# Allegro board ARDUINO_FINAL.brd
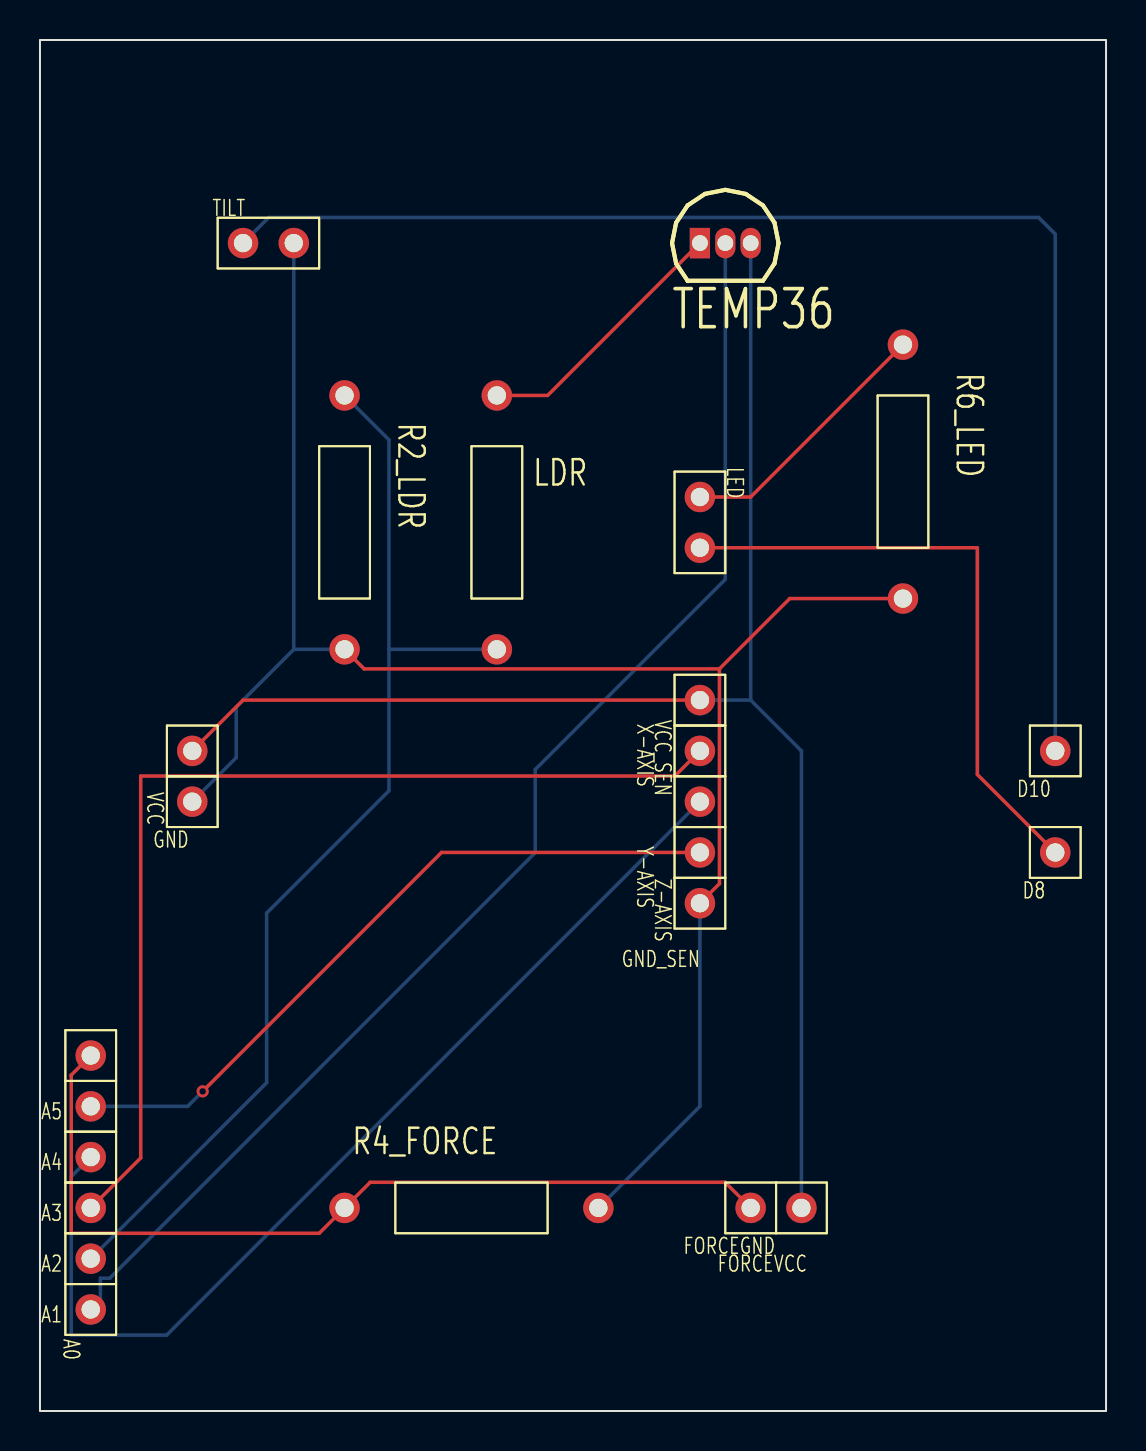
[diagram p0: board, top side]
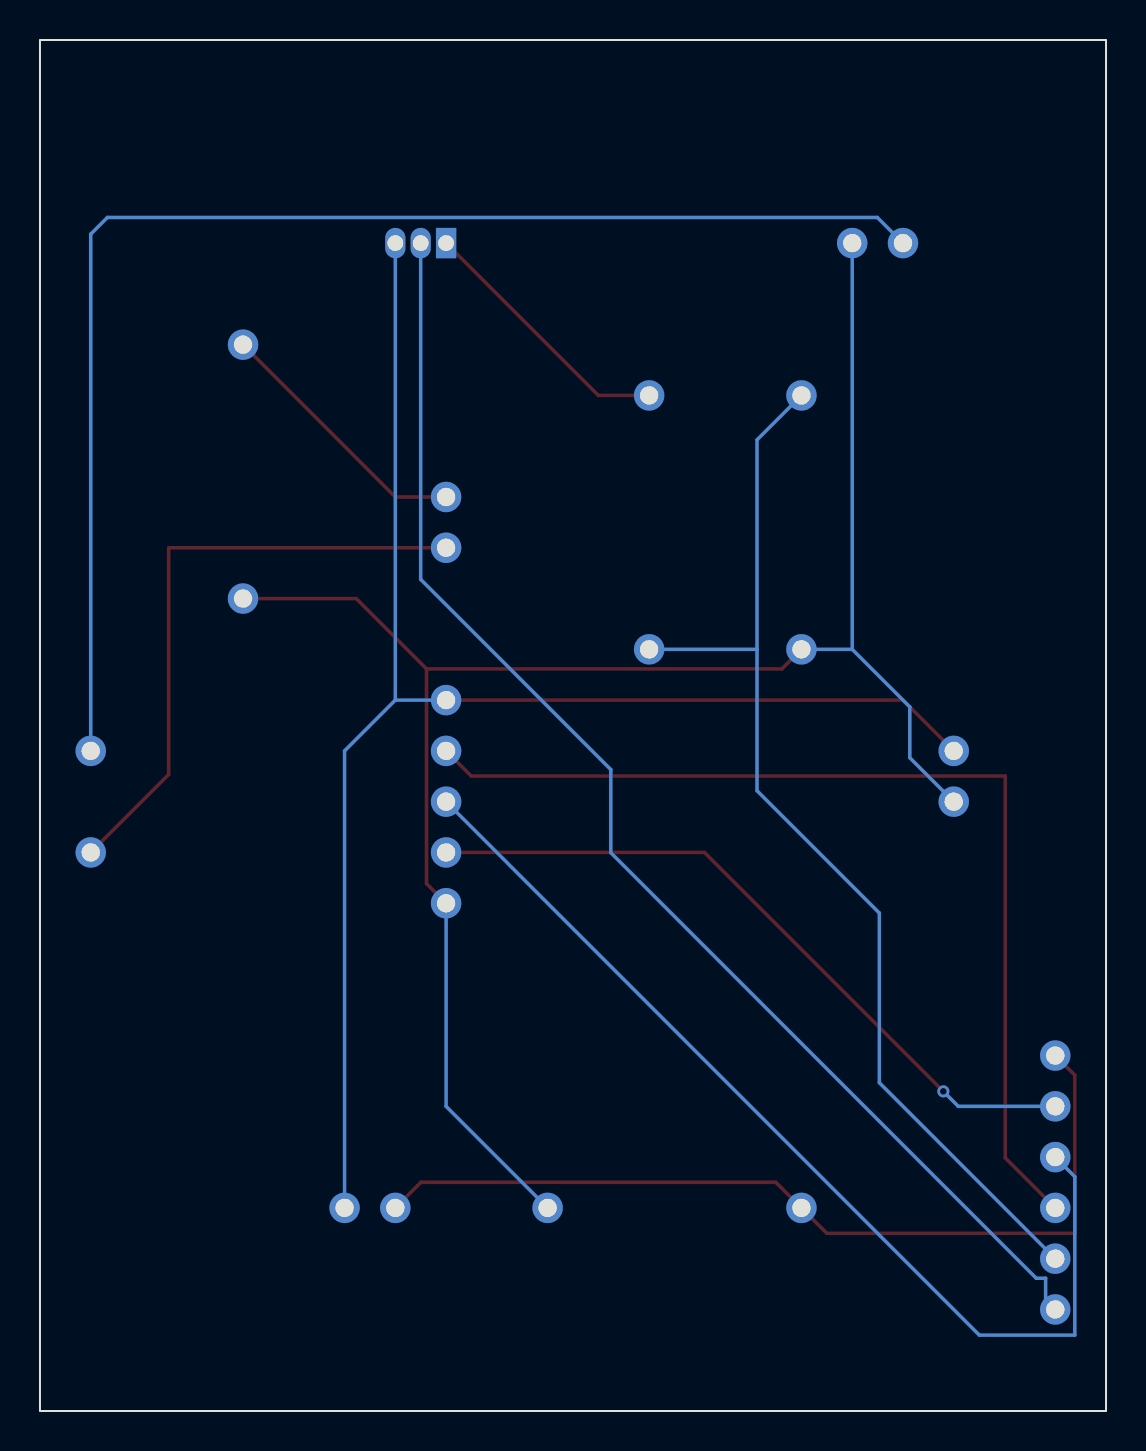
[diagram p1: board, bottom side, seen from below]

Outline 53.34 x 68.58 mm; copper layers: TOP, BOTTOM. Coordinates in mm from the lower left corner of the outline.
Outline path: rectangle 0,0 53.34,68.58

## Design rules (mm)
constraint set DEFAULT: min track width 0.178

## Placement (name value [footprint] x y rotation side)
A0  Jump1  [JUMPER1]  2.54 5.08 0 top
A1  Jump1  [JUMPER1]  2.54 7.62 0 top
A2  Jump1  [JUMPER1]  2.54 10.16 0 top
A3  Jump1  [JUMPER1]  2.54 12.7 0 top
A4  Jump1  [JUMPER1]  2.54 15.24 0 top
A5  Jump1  [JUMPER1]  2.54 17.78 0 top
D8  Jump1  [JUMPER1]  50.8 27.94 0 top
D10  Jump1  [JUMPER1]  50.8 33.02 0 top
FORCEGND  Jump1  [JUMPER1]  35.56 10.16 0 top
FORCEVCC  Jump1  [JUMPER1]  38.1 10.16 0 top
GND  Jump1  [JUMPER1]  7.62 30.48 0 top
GND_SEN  Jump1  [JUMPER1]  33.02 25.4 0 top
LDR  1g  [RES500]  22.86 50.8 0 top
LED  Jump2  [JUMPER2]  33.02 45.72 270 top
R2_LDR  10k  [RES500]  15.24 50.8 0 top
R4_FORCE  10k  [RES500]  15.24 10.16 90 top
R6_LED  220  [RES500]  43.18 53.34 0 top
TEMP36  BC547  [TO92]  33.02 58.42 0 top
TILT  Jump2  [JUMPER2]  10.16 58.42 0 top
VCC  Jump1  [JUMPER1]  7.62 33.02 0 top
VCC_SEN  Jump1  [JUMPER1]  33.02 35.56 0 top
X-AXIS  Jump1  [JUMPER1]  33.02 33.02 0 top
Y-AXIS  Jump1  [JUMPER1]  33.02 30.48 0 top
Z-AXIS  Jump1  [JUMPER1]  33.02 27.94 0 top

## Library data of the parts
A0-A5 D8 D10 FORCEGND FORCEVCC GND GND_SEN VCC VCC_SEN X-AXIS Y-AXIS Z-AXIS = Jump1: User Part Number: ***
LDR R2_LDR R4_FORCE R6_LED = R: Tolerance: ***; User Part Number: ***
LED TILT = Jump2: User Part Number: ***
TEMP36 = BC547

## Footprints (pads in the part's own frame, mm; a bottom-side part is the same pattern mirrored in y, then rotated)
JUMPER1
  round 1.524 hole 0.914: 1(0,0)
JUMPER2
  round 1.524 hole 0.914: 1(0,0) 2(2.54,0)
RES500
  round 1.524 hole 0.914: 1(0,-12.7) 2(0,0)
TO92
  rect 1.016x1.524 hole 0.787: 1(0,0)
  oval 1.016x1.524 hole 0.787: 2(1.27,0) 3(2.54,0)

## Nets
N9071070: A0.1(PIN1) TEMP36.2
N9071079: LDR.2 TEMP36.1(EMITTER)
N9071083: A1.1(PIN1) LDR.1 R2_LDR.2
N9071144: A2.1(PIN1) X-AXIS.1(PIN1)
N9071148: A3.1(PIN1) Y-AXIS.1(PIN1)
N9071152: A4.1(PIN1) Z-AXIS.1(PIN1)
N9071371: A5.1(PIN1) FORCEGND.1(PIN1) R4_FORCE.2
N9071390: FORCEVCC.1(PIN1) TEMP36.3 VCC.1(PIN1) VCC_SEN.1(PIN1)
N9071630: GND.1(PIN1) GND_SEN.1(PIN1) R2_LDR.1 R4_FORCE.1 R6_LED.1 TILT.2(PIN2)
N9071754: D10.1(PIN1) TILT.1
N9071826: D8.1(PIN1) LED.2(PIN2)
N9071858: LED.1 R6_LED.2

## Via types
v1: diameter 0.61, hole 0.33, TOP to BOTTOM, 1 via

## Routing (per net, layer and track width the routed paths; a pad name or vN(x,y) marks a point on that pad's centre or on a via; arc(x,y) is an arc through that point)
N9071070: length 66.8
  BOTTOM w0.178: TEMP36.2 34.29,41.6 24.78,32.09 24.78,27.93 3.49,6.64 3.02,6.64 3.02,5.56 A0.1
N9071079: length 13.3
  TOP w0.178: LDR.2 25.4,50.8 TEMP36.1
N9071083: length 55.7
  BOTTOM w0.178: A1.1 11.34,16.42 11.34,24.91 17.46,31.03 17.46,38.1 ; LDR.1 17.46,38.1 ; 17.46,38.1 17.46,48.58 R2_LDR.2
N9071144: length 51.1
  TOP w0.178: X-AXIS.1 31.76,31.76 5.04,31.76 5.04,12.66 A2.1
N9071148: length 51.8
  BOTTOM w0.178: Y-AXIS.1 6.34,3.8 1.56,3.8 1.56,11.72 A3.1
N9071152: length 35.7
  TOP w0.178: v1(8.14,15.99) 20.09,27.94 Z-AXIS.1
  BOTTOM w0.178: A4.1 7.39,15.24 v1(8.14,15.99)
N9071371: length 44.9
  TOP w0.178: A5.1 1.56,16.8 1.56,8.89 13.97,8.89 R4_FORCE.2 16.52,11.44 34.28,11.44 FORCEGND.1
N9071390: length 78.3
  TOP w0.178: VCC.1 10.16,35.56 VCC_SEN.1
  BOTTOM w0.178: FORCEVCC.1 38.1,33.02 35.56,35.56 ; 35.56,35.56 TEMP36.3 ; 35.56,35.56 VCC_SEN.1
N9071630: length 91.9
  TOP w0.178: 34,37.12 16.22,37.12 R2_LDR.1 ; 34,37.12 34,26.38 GND_SEN.1 ; 34,37.12 37.52,40.64 R6_LED.1
  BOTTOM w0.178: GND.1 9.82,32.68 9.82,35.22 12.7,38.1 ; 12.7,38.1 R2_LDR.1 ; 12.7,38.1 TILT.2 ; R4_FORCE.1 33.02,15.24 GND_SEN.1
N9071754: length 67.4
  BOTTOM w0.178: D10.1 50.8,58.87 49.97,59.7 11.44,59.7 TILT.1
N9071826: length 30.7
  TOP w0.178: LED.2 46.9,43.18 46.9,31.84 D8.1
N9071858: length 13.3
  TOP w0.178: LED.1 35.56,45.72 R6_LED.2

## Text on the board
User.Comments: Manzur & Swetha
USER_PART_NUM_TOP: FIGURE | FINISHED_SIZE | 13.0 | 31.0 | 36.0 | DRILL CHART: TOP to BOTTOM | ALL UNITS ARE IN MILS | PLATED | QTY | 1 | 3 | 29
